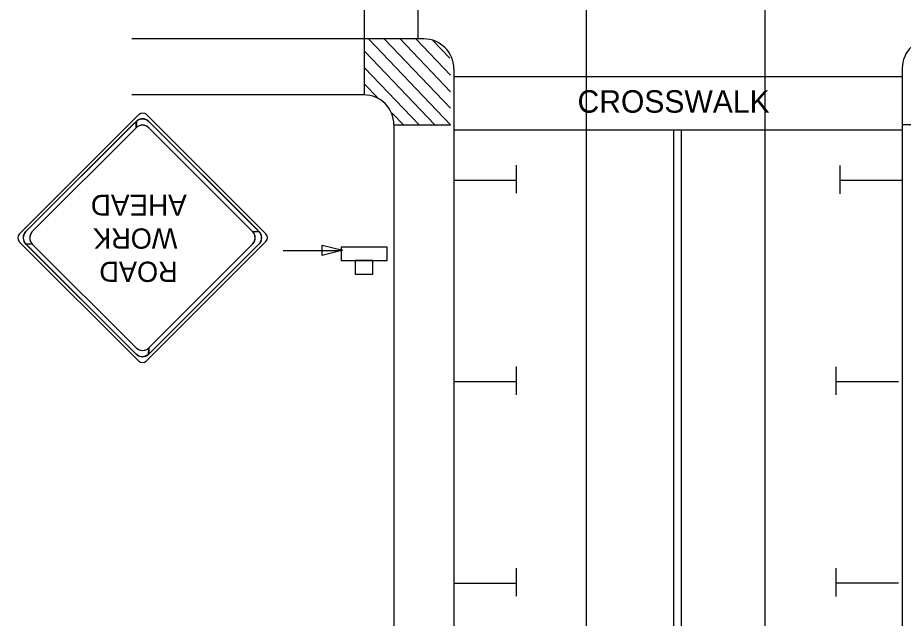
# Model space of a CAD drawing. Extents: x 12.69 to 19.62, y 5.94 to 15.87.
# Drawn here: x 13.007 to 15.342, y 12.107 to 13.692 of the extents above; entities that cross this region are included whole.
import ezdxf

# ---------------------------------------------------------------- set-up
doc = ezdxf.new("R2010")
doc.units = 0
for name, color, linetype in [('DETL-LINE', 7, 'Continuous'), ('V7_LEVEL_1', 7, 'Continuous'), ('V7_LEVEL_10', 7, 'Continuous')]:
    doc.layers.add(name, color=color, linetype=linetype)

msp = doc.modelspace()

# ---------------------------------------------------------------- linework, layer by layer
at = {"layer": 'DETL-LINE'}
for p, q in [((13.9215, 13.489), (13.9215, 13.6472)), ((14.1481, 13.4099), (13.932, 13.6362)), ((14.1481, 13.4534), (13.9735, 13.6362)), ((14.1481, 13.4968), (14.015, 13.6362)), ((14.1481, 13.5402), (14.0565, 13.6362)), ((14.1461, 13.5858), (14.1014, 13.6325)), ((14.1066, 13.4099), (13.9215, 13.6038)), ((14.0652, 13.4099), (13.9215, 13.5603)), ((13.9555, 13.4813), (13.9215, 13.5169)), ((14.0237, 13.4099), (13.9944, 13.4406)), ((14.0006, 13.4099), (14.1481, 13.4099)), ((15.4921, 13.4096), (15.3398, 13.4096))]:
    msp.add_line(p, q, dxfattribs=at)
at = {"layer": 'V7_LEVEL_1'}
for p, q in [((14.5059, 14.9247), (14.5059, 9.3607)), ((14.9772, 14.9247), (14.9772, 9.4166)), ((13.9206, 14.3983), (13.9206, 13.6362)), ((14.0624, 13.6362), (14.0624, 14.3983)), ((14.0779, 13.6362), (13.3076, 13.6362)), ((14.1569, 13.5569), (14.1569, 10.0715)), ((15.3398, 13.5589), (15.3398, 8.7364)), ((14.1569, 13.5371), (15.3398, 13.5371)), ((13.9197, 13.4886), (13.3076, 13.4886)), ((13.3264, 13.4366), (13.0106, 13.1206)), ((13.6612, 13.1214), (13.346, 13.4366)), ((13.0283, 13.1281), (13.3188, 13.4186)), ((13.3523, 13.4186), (13.6427, 13.1281)), ((13.9987, 13.4095), (13.9987, 10.0715)), ((13.3188, 13.4018), (13.045, 13.1281)), ((13.626, 13.1281), (13.3522, 13.4018)), ((15.3398, 13.3953), (14.1569, 13.3953)), ((14.7362, 13.3953), (14.7362, 10.0715)), ((14.7568, 13.3953), (14.7568, 10.0715)), ((14.3214, 13.3034), (14.3214, 13.2292)), ((15.1753, 13.3019), (15.1753, 13.2622)), ((14.1569, 13.2637), (14.3214, 13.2637)), ((15.3398, 13.2622), (15.1753, 13.2622)), ((15.1753, 13.2622), (15.1753, 13.2277)), ((13.0106, 13.1011), (13.3257, 12.786)), ((13.3188, 12.8041), (13.0283, 13.0946)), ((13.045, 13.0946), (13.3188, 12.8209)), ((13.3453, 12.786), (13.6612, 13.1018)), ((13.6427, 13.0946), (13.3523, 12.8041)), ((13.3523, 12.8209), (13.626, 13.0946)), ((14.3214, 12.7713), (14.3214, 12.6971)), ((15.1647, 12.771), (15.1647, 12.7313)), ((14.1569, 12.7317), (14.3214, 12.7317)), ((15.3293, 12.7313), (15.1647, 12.7313)), ((15.1647, 12.7313), (15.1647, 12.6968)), ((14.3214, 12.2393), (14.3214, 12.1651)), ((15.1647, 12.239), (15.1647, 12.1994)), ((14.1569, 12.1997), (14.3214, 12.1997)), ((15.3293, 12.1994), (15.1647, 12.1994)), ((15.1647, 12.1994), (15.1647, 12.1648))]:
    msp.add_line(p, q, dxfattribs=at)
for points in [[(13.0283, 13.1281), (13.3104, 13.4102), (13.3198, 13.4195), (13.3188, 13.4018), (13.045, 13.1281), (13.0407, 13.1222), (13.0382, 13.1135), (13.0388, 13.1054), (13.041, 13.0999), (13.045, 13.0946), (13.0283, 13.0946), (13.0236, 13.1014), (13.0214, 13.1105), (13.0221, 13.1172), (13.0242, 13.1226)], [(13.3522, 13.4185), (13.6343, 13.1364), (13.6437, 13.127), (13.626, 13.1281), (13.3523, 13.4018), (13.3463, 13.4061), (13.3376, 13.4087), (13.3295, 13.408), (13.324, 13.4058), (13.3188, 13.4018), (13.3188, 13.4185), (13.3255, 13.4233), (13.3346, 13.4255), (13.3413, 13.4248), (13.3468, 13.4226)], [(13.6427, 13.0946), (13.3606, 12.8125), (13.3512, 12.8031), (13.3522, 12.8209), (13.626, 13.0946), (13.6303, 13.1005), (13.6328, 13.1092), (13.6321, 13.1173), (13.6299, 13.1228), (13.626, 13.1281), (13.6427, 13.1281), (13.6475, 13.1213), (13.6496, 13.1122), (13.6489, 13.1055), (13.6467, 13.1001)], [(13.3188, 12.8042), (13.0367, 13.0862), (13.0273, 13.0957), (13.045, 13.0946), (13.3188, 12.8209), (13.3247, 12.8165), (13.3334, 12.814), (13.3414, 12.8147), (13.347, 12.8169), (13.3522, 12.8209), (13.3522, 12.8042), (13.3454, 12.7994), (13.3363, 12.7972), (13.3297, 12.7979), (13.3242, 12.8001)], [(13.9806, 13.0517), (13.9806, 13.0865), (13.8594, 13.0865), (13.8594, 13.0517)], [(13.8966, 13.0156), (13.9433, 13.0156), (13.9433, 13.0517), (13.8966, 13.0517)]]:
    msp.add_lwpolyline(points, close=True, dxfattribs=at)
for points in [[(14.5059, 13.2354), (14.5059, 13.1288)], [(14.9772, 13.2354), (14.9772, 13.1288)], [(14.5059, 12.809), (14.5059, 12.7023)], [(14.9772, 12.809), (14.9772, 12.7023)], [(14.5059, 12.3825), (14.5059, 12.2759)], [(14.9772, 12.3825), (14.9772, 12.2759)]]:
    msp.add_lwpolyline(points, dxfattribs=at)
for centre, radius, start, end in [((14.0778, 13.5571), 0.0791, 0, 90), ((15.4187, 13.5589), 0.0789, 90, 180), ((13.9197, 13.4095), 0.0791, 0, 90), ((13.3362, 13.4268), 0.0138, 45, 135), ((13.3355, 13.3851), 0.0237, 45, 135), ((13.3355, 13.4018), 0.0237, 45, 135), ((13.045, 13.1113), 0.0237, 135, 225), ((13.0618, 13.1114), 0.0237, 135, 225), ((13.6092, 13.1113), 0.0237, 315, 45), ((13.626, 13.1113), 0.0237, 315, 45), ((13.0203, 13.1109), 0.0138, 135, 225), ((13.6514, 13.1116), 0.0138, 315, 45), ((13.3355, 12.8376), 0.0237, 225, 315), ((13.3355, 12.8209), 0.0237, 225, 315), ((13.3355, 12.7957), 0.0138, 225, 315)]:
    msp.add_arc(centre, radius, start, end, dxfattribs=at)
at = {"layer": 'V7_LEVEL_10'}
msp.add_line((13.7069, 13.0779), (13.8594, 13.0782), dxfattribs=at)
msp.add_lwpolyline([(13.864, 13.0784), (13.8098, 13.065), (13.8098, 13.0919)], close=True, dxfattribs=at)

# ---------------------------------------------------------------- texts
at = {"layer": 'V7_LEVEL_1'}
for s, height, rotation, p in [('CROSSWALK', 0.0593, 360, (14.4831, 13.4415)), ('AHEAD', 0.05487, 180, (13.4523, 13.2248)), ('WORK', 0.05344, 180, (13.4277, 13.1361)), ('ROAD', 0.05344, 180, (13.4284, 13.0484))]:
    msp.add_text(s, height=height, rotation=rotation, dxfattribs=at).set_placement(p)

doc.saveas('drawing.dxf')
